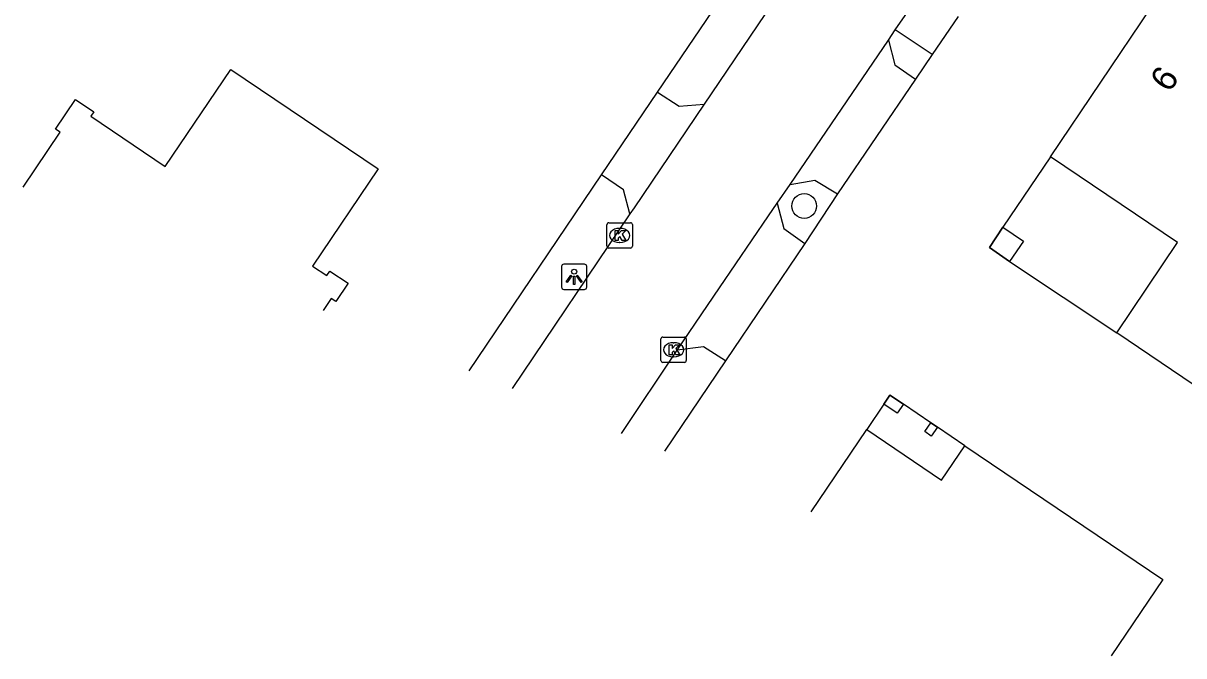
# Model space of a CAD drawing. Extents: x 163863 to 164644, y 379566 to 382155.
# Drawn here: x 164129.01 to 164174.78, y 381775.46 to 381800.42 of the extents above; entities that cross this region are included whole.
import ezdxf

# ---------------------------------------------------------------- set-up
doc = ezdxf.new("R2010")
doc.units = 0
for name, color, linetype in [('IMGEO_Boom', 7, 'Continuous'), ('IMGEO_Groenvoorziening', 7, 'Continuous'), ('IMGEO_Kolk', 7, 'Continuous'), ('IMGEO_Lichtpunt', 7, 'Continuous'), ('IMGEO_Pand', 7, 'Continuous'), ('IMGEO_Pand_nummerreeks', 7, 'Continuous'), ('IMGEO_Pand_overbouw', 7, 'Continuous'), ('IMGEO_Rijbaan_lokaal_open', 7, 'Continuous'), ('IMGEO_Voetpad_halfverhard', 7, 'Continuous'), ('IMGEO_Voetpad_open', 7, 'Continuous')]:
    doc.layers.add(name, color=color, linetype=linetype)

msp = doc.modelspace()

# ---------------------------------------------------------------- linework, layer by layer
at = {"layer": 'IMGEO_Boom'}
msp.add_circle((164159.808, 381793.206), 0.489, dxfattribs=at)
at = {"layer": 'IMGEO_Groenvoorziening'}
msp.add_lwpolyline([(164161.124, 381793.688), (164159.838, 381791.733)], dxfattribs=at)
at = {"layer": 'IMGEO_Kolk'}
for p, q in [((164152.031, 381791.62), (164152.031, 381792.472)), ((164152.106, 381792.546), (164152.958, 381792.546)), ((164153.032, 381792.472), (164153.032, 381791.62)), ((164152.519, 381792.326), (164152.544, 381792.326)), ((164152.958, 381791.546), (164152.106, 381791.546)), ((164152.542, 381791.766), (164152.517, 381791.766)), ((164154.157, 381787.109), (164154.157, 381787.961)), ((164154.232, 381788.035), (164155.084, 381788.035)), ((164155.158, 381787.961), (164155.158, 381787.109)), ((164154.645, 381787.815), (164154.67, 381787.815)), ((164155.084, 381787.035), (164154.232, 381787.035)), ((164154.668, 381787.255), (164154.643, 381787.255))]:
    msp.add_line(p, q, dxfattribs=at)
for points in [[(164152.031, 381791.62), (164152.031, 381792.472)], [(164152.106, 381792.546), (164152.958, 381792.546)], [(164153.032, 381792.472), (164153.032, 381791.62)], [(164152.352, 381792.246), (164152.475, 381792.246), (164152.475, 381792.095), (164152.605, 381792.246), (164152.769, 381792.246), (164152.623, 381792.095), (164152.776, 381791.846), (164152.624, 381791.846), (164152.539, 381792.01), (164152.475, 381791.943), (164152.475, 381791.846), (164152.352, 381791.846), (164152.352, 381792.246)], [(164152.958, 381791.546), (164152.106, 381791.546)], [(164154.157, 381787.109), (164154.157, 381787.961)], [(164154.232, 381788.035), (164155.084, 381788.035)], [(164155.158, 381787.961), (164155.158, 381787.109)], [(164154.478, 381787.735), (164154.601, 381787.735), (164154.601, 381787.584), (164154.731, 381787.735), (164154.895, 381787.735), (164154.749, 381787.584), (164154.902, 381787.335), (164154.75, 381787.335), (164154.665, 381787.499), (164154.601, 381787.432), (164154.601, 381787.335), (164154.478, 381787.335), (164154.478, 381787.735)], [(164155.084, 381787.035), (164154.232, 381787.035)]]:
    msp.add_lwpolyline(points, dxfattribs=at)
for centre, start, end in [((164152.108, 381792.47), 91.552, 178.448), ((164152.108, 381792.47), 91.552, 178.448), ((164152.956, 381792.47), 1.552, 88.448), ((164152.956, 381792.47), 1.552, 88.448), ((164152.108, 381791.622), 181.552, 268.448), ((164152.108, 381791.622), 181.552, 268.448), ((164152.956, 381791.622), 271.552, 358.448), ((164152.956, 381791.622), 271.552, 358.448), ((164154.234, 381787.959), 91.552, 178.448), ((164154.234, 381787.959), 91.552, 178.448), ((164155.082, 381787.959), 1.552, 88.448), ((164155.082, 381787.959), 1.552, 88.448), ((164154.234, 381787.111), 181.552, 268.448), ((164154.234, 381787.111), 181.552, 268.448), ((164155.082, 381787.111), 271.552, 358.448), ((164155.082, 381787.111), 271.552, 358.448)]:
    msp.add_arc(centre, 0.0765, start, end, dxfattribs=at)
for centre, major_axis, ratio, start_param, end_param in [((164152.518, 381792.046), (-0.387, 0.002), 0.722429, 4.712389, 7.853982), ((164152.543, 381792.046), (-0.39, 0.002), 0.717154, 1.570796, 4.712389), ((164154.644, 381787.535), (-0.387, 0.002), 0.722429, 4.712389, 7.853982), ((164154.669, 381787.535), (-0.39, 0.002), 0.717154, 1.570796, 4.712389)]:
    msp.add_ellipse(centre, major_axis=major_axis, ratio=ratio, start_param=start_param, end_param=end_param, dxfattribs=at)
at = {"layer": 'IMGEO_Lichtpunt'}
for p, q in [((164150.237, 381790.818), (164150.237, 381790.011)), ((164150.237, 381790.818), (164150.237, 381790.011)), ((164151.139, 381790.913), (164150.331, 381790.913)), ((164151.139, 381790.913), (164150.331, 381790.913)), ((164151.233, 381790.011), (164151.233, 381790.818)), ((164151.233, 381790.011), (164151.233, 381790.818)), ((164150.331, 381789.917), (164151.139, 381789.917)), ((164150.331, 381789.917), (164151.139, 381789.917))]:
    msp.add_line(p, q, dxfattribs=at)
for points in [[(164150.611, 381790.482), (164150.65, 381790.454), (164150.462, 381790.192), (164150.424, 381790.219), (164150.611, 381790.482)], [(164150.713, 381790.434), (164150.76, 381790.434), (164150.76, 381790.112), (164150.713, 381790.112), (164150.713, 381790.434)], [(164150.823, 381790.454), (164150.861, 381790.481), (164151.048, 381790.219), (164151.009, 381790.191), (164150.823, 381790.454)]]:
    msp.add_lwpolyline(points, dxfattribs=at)
msp.add_circle((164150.736, 381790.616), 0.0994, dxfattribs=at)
for centre, start, end in [((164150.331, 381790.818), 90, 180), ((164150.331, 381790.818), 90, 180), ((164151.139, 381790.818), 0, 90), ((164151.139, 381790.818), 0, 90), ((164150.331, 381790.011), 180, 270), ((164150.331, 381790.011), 180, 270), ((164151.139, 381790.011), 270, 0), ((164151.139, 381790.011), 270, 360)]:
    msp.add_arc(centre, 0.0946, start, end, dxfattribs=at)
at = {"layer": 'IMGEO_Pand'}
for points in [[(164172.134, 381788.209), (164174.528, 381791.769), (164169.519, 381795.147), (164175.479, 381804.003), (164188.769, 381795.078), (164180.351, 381782.639), (164172.134, 381788.209)], [(164130.462, 381796.115), (164130.28, 381796.238), (164131.074, 381797.415), (164131.795, 381796.928), (164131.672, 381796.746), (164134.606, 381794.765), (164137.191, 381798.595), (164143.005, 381794.672), (164140.421, 381790.832), (164140.977, 381790.459), (164141.1, 381790.642), (164141.822, 381790.157), (164141.339, 381789.437), (164141.156, 381789.559), (164140.833, 381789.08)], [(164129.005, 381793.957), (164130.462, 381796.115)], [(164167.116, 381791.569), (164167.65, 381792.375), (164168.456, 381791.821), (164167.909, 381791.024), (164167.116, 381791.569)], [(164162.954, 381785.391), (164163.193, 381785.749), (164163.722, 381785.395), (164163.482, 381785.038), (164162.954, 381785.391)], [(164164.565, 381784.304), (164164.809, 381784.658), (164165.064, 381784.482), (164164.821, 381784.128), (164164.565, 381784.304)], [(164160.086, 381781.142), (164162.28, 381784.386), (164165.229, 381782.391), (164166.15, 381783.749), (164173.951, 381778.472), (164171.914, 381775.46)]]:
    msp.add_lwpolyline(points, dxfattribs=at)
at = {"layer": 'IMGEO_Pand_overbouw'}
for points in [[(164167.909, 381791.024), (164172.134, 381788.209), (164174.528, 381791.769), (164169.519, 381795.147), (164167.65, 381792.375), (164167.116, 381791.569)], [(164165.229, 381782.391), (164166.15, 381783.749), (164165.064, 381784.482), (164164.809, 381784.658), (164163.722, 381785.395), (164163.193, 381785.749), (164162.954, 381785.391), (164162.28, 381784.386)]]:
    msp.add_lwpolyline(points, close=True, dxfattribs=at)
at = {"layer": 'IMGEO_Rijbaan_lokaal_open'}
for points in [[(164160.068, 381803.456), (164155.87, 381797.223)], [(164163.391, 381800.153), (164164.432, 381801.664)], [(164159.256, 381794.06), (164163.13, 381799.747)], [(164163.13, 381799.747), (164163.391, 381800.153)], [(164163.13, 381799.747), (164163.386, 381798.783), (164164.201, 381798.208)], [(164164.201, 381798.208), (164161.124, 381793.688)], [(164151.818, 381794.439), (164154.029, 381797.699)], [(164154.029, 381797.699), (164154.884, 381797.145), (164155.87, 381797.223)], [(164155.87, 381797.223), (164153.097, 381793.141), (164152.932, 381792.897)], [(164152.932, 381792.897), (164152.678, 381793.841), (164151.818, 381794.439)], [(164158.744, 381793.325), (164159.256, 381794.06)], [(164159.256, 381794.06), (164160.233, 381794.231), (164161.124, 381793.688)], [(164152.932, 381792.897), (164148.287, 381786.006)], [(164154.795, 381787.522), (164156.465, 381789.976), (164158.404, 381792.826), (164158.744, 381793.325)], [(164158.744, 381793.325), (164159.007, 381792.319), (164159.838, 381791.733)], [(164159.838, 381791.733), (164156.707, 381787.104)], [(164152.597, 381784.229), (164154.795, 381787.522)], [(164156.707, 381787.104), (164155.842, 381787.656), (164154.795, 381787.522)]]:
    msp.add_lwpolyline(points, dxfattribs=at)
at = {"layer": 'IMGEO_Voetpad_halfverhard'}
for points in [[(164154.029, 381797.699), (164158.614, 381804.471)], [(164164.857, 381799.186), (164164.201, 381798.208)], [(164146.594, 381786.705), (164151.818, 381794.439)], [(164156.707, 381787.104), (164154.295, 381783.529)]]:
    msp.add_lwpolyline(points, dxfattribs=at)
at = {"layer": 'IMGEO_Voetpad_open'}
for points in [[(164165.885, 381800.687), (164164.857, 381799.186)], [(164164.857, 381799.186), (164163.391, 381800.153)]]:
    msp.add_lwpolyline(points, dxfattribs=at)

# ---------------------------------------------------------------- texts
at = {"layer": 'IMGEO_Pand_nummerreeks'}
msp.add_text('6', height=1, rotation=55.8634, dxfattribs=at).set_placement((164174.214, 381797.648))

doc.saveas('drawing.dxf')
